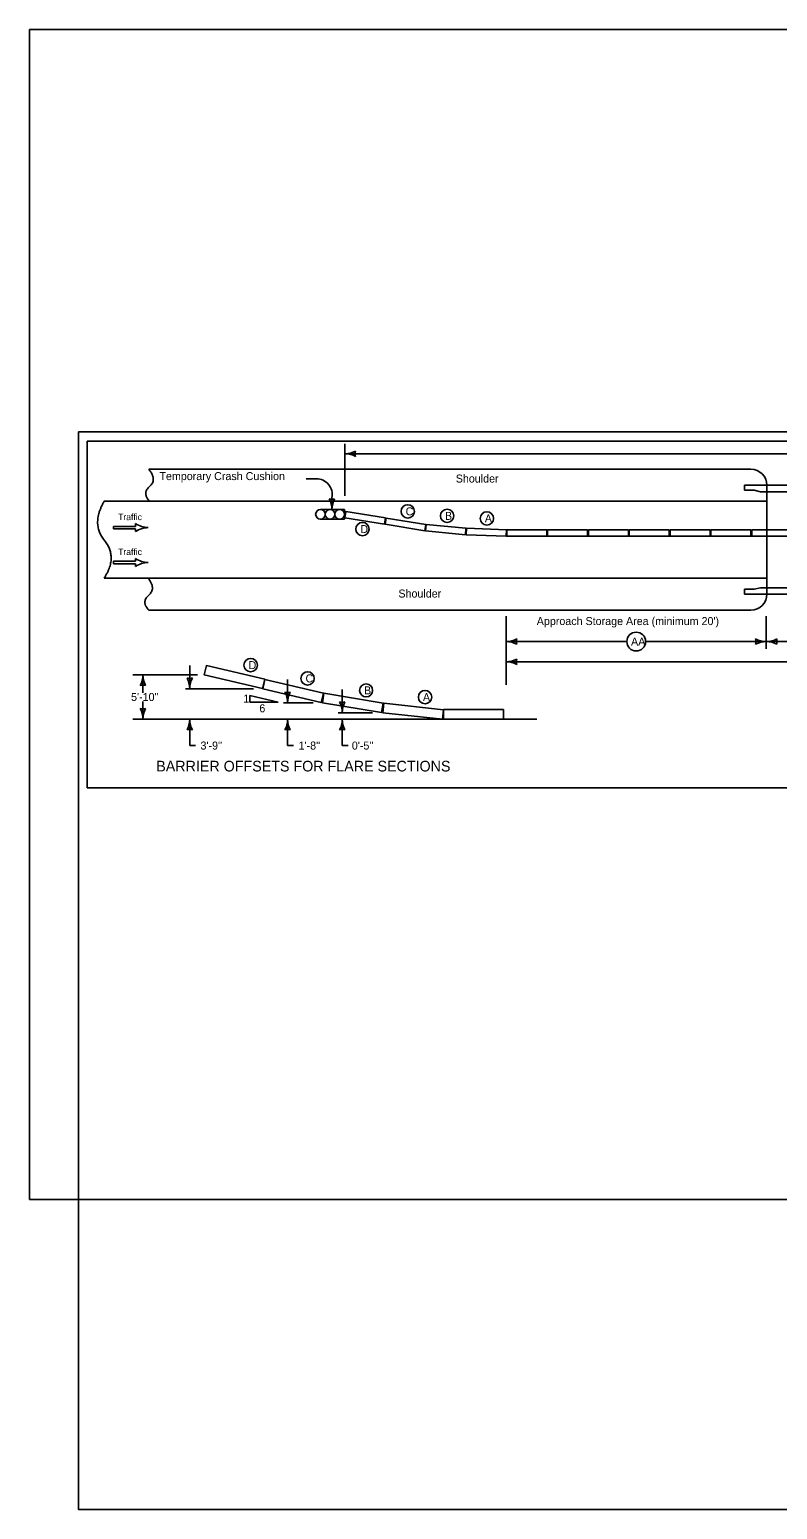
# Model space of a CAD drawing. Extents: x 10041 to 81668, y 7924 to 11018.
# Drawn here: x 10041 to 11442, y 7924 to 10698 of the extents above; entities that cross this region are included whole.
import ezdxf

# ---------------------------------------------------------------- set-up
doc = ezdxf.new("R2010")
doc.units = 0
for name, color, linetype in [('dsnCellElements', 7, 'Continuous'), ('Level 1', 7, 'Continuous'), ('Level 10', 7, 'Continuous'), ('Level 12', 7, 'Continuous'), ('Level 5', 7, 'Continuous'), ('Level 6', 7, 'Continuous'), ('SheetBorder', 7, 'Continuous'), ('ShtPlotIdentification', 7, 'Continuous')]:
    doc.layers.add(name, color=color, linetype=linetype)

msp = doc.modelspace()

# ---------------------------------------------------------------- linework, layer by layer
at = {"layer": 'dsnCellElements'}
msp.add_lwpolyline([(10041.2, 8505), (13362.1, 8505), (13362.1, 10698.4), (10041.2, 10698.4)], close=True, dxfattribs=at)
at = {"layer": 'Level 1'}
for p, q in [((10632, 9921.7), (10632, 9824.3)), ((10632, 9903.1), (11510.6, 9903.1)), ((10264.4, 9874.1), (11392.9, 9874.1)), ((10578.3, 9856.4), (10559.5, 9856.4)), ((11422.9, 9844.1), (11380.9, 9844.1)), ((11380.9, 9844.1), (11380.9, 9835.1)), ((11380.9, 9835.1), (11398.9, 9835.1)), ((11410.9, 9832.1), (11398.9, 9835.1)), ((11422.9, 9832.1), (11410.9, 9832.1)), ((11422.9, 9844.1), (11422.9, 9640.1)), ((11422.9, 9844.1), (11568.9, 9844.1)), ((11422.9, 9832.1), (11568.9, 9832.1)), ((10180.8, 9814.1), (11422.9, 9814.1)), ((10586.2, 9798.5), (10631.2, 9798.5)), ((10607.8, 9821), (10607.8, 9798.5)), ((10631.2, 9798.5), (10631.2, 9780.5)), ((10239.6, 9767), (10198.4, 9767)), ((10198.4, 9767), (10198.4, 9762.5)), ((10239.6, 9772.2), (10239.6, 9767)), ((10631.2, 9780.5), (10586.2, 9780.5)), ((10630, 9786.2), (10631.2, 9786)), ((10631.7, 9782.5), (10631.7, 9782.5)), ((10198.4, 9762.5), (10239.6, 9762.5)), ((10239.6, 9762.5), (10239.6, 9757.2)), ((10263.6, 9764.7), (10263.6, 9764.7)), ((10239.6, 9701.5), (10198.4, 9701.5)), ((10198.4, 9701.5), (10198.4, 9697)), ((10198.4, 9697), (10239.6, 9697)), ((10239.6, 9706.8), (10239.6, 9701.5)), ((10239.6, 9697), (10239.6, 9691.8)), ((10263.6, 9699.3), (10263.6, 9699.3)), ((10180.8, 9670.1), (11422.9, 9670.1)), ((11380.9, 9649.1), (11398.9, 9649.1)), ((11380.9, 9640.1), (11380.9, 9649.1)), ((11422.9, 9640.1), (11380.9, 9640.1)), ((11410.9, 9652.1), (11398.9, 9649.1)), ((11422.9, 9652.1), (11410.9, 9652.1)), ((11422.9, 9652.1), (11568.9, 9652.1)), ((11422.9, 9640.1), (11568.9, 9640.1)), ((10264.4, 9610.1), (11392.9, 9610.1)), ((10934.2, 9598.9), (10934.2, 9469.7)), ((11421.7, 9598.9), (11421.7, 9537.6)), ((10934.2, 9551.1), (11160.3, 9551.1)), ((11195.6, 9551.1), (11421.7, 9551.1)), ((11421.7, 9551.1), (11564.9, 9551.1)), ((10355.7, 9488.7), (10234.5, 9488.7)), ((10253.5, 9488.7), (10253.5, 9455.2)), ((10341.1, 9506.2), (10341.1, 9462.7)), ((10934.2, 9513.2), (11525, 9513.2)), ((10460.6, 9462.7), (10333.4, 9462.7)), ((10524.7, 9479.8), (10524.7, 9436.3)), ((10627.1, 9461.2), (10627.1, 9417.7)), ((10253.5, 9438.9), (10253.5, 9405.4)), ((10572.5, 9436.3), (10516.9, 9436.3)), ((10991.9, 9405.4), (10234.5, 9405.4)), ((10341.1, 9405.4), (10341.1, 9356.1)), ((10524.7, 9405.4), (10524.7, 9356.1)), ((10683.4, 9417.7), (10619.3, 9417.7)), ((10627.1, 9405.4), (10627.1, 9378.5)), ((10627.1, 9378.5), (10627.1, 9356.1)), ((10341.1, 9356.1), (10352.3, 9356.1)), ((10524.7, 9356.1), (10535.8, 9356.1)), ((10627.1, 9356.1), (10638.2, 9356.1))]:
    msp.add_line(p, q, dxfattribs=at)
for points in [[(10708, 9783), (10634, 9795.1), (10632, 9783.2), (10706, 9771.1)], [(10783.5, 9770.6), (10709.5, 9782.7), (10707.5, 9770.9), (10781.5, 9758.7)], [(10858.9, 9763.4), (10784.2, 9770.5), (10783.1, 9758.5), (10857.8, 9751.4)], [(10934.7, 9760.4), (10859.7, 9763.4), (10859.3, 9751.4), (10934.2, 9748.4)], [(10935.4, 9760.4), (11010.4, 9760.4), (11010.4, 9748.4), (10935.4, 9748.4)], [(11011.9, 9760.4), (11086.9, 9760.4), (11086.9, 9748.4), (11011.9, 9748.4)], [(11088.4, 9760.4), (11163.4, 9760.4), (11163.4, 9748.4), (11088.4, 9748.4)], [(11164.9, 9760.4), (11239.9, 9760.4), (11239.9, 9748.4), (11164.9, 9748.4)], [(11241.4, 9760.4), (11316.4, 9760.4), (11316.4, 9748.4), (11241.4, 9748.4)], [(11317.9, 9760.4), (11392.9, 9760.4), (11392.9, 9748.4), (11317.9, 9748.4)], [(11394.4, 9760.4), (11469.4, 9760.4), (11469.4, 9748.4), (11394.4, 9748.4)], [(10481.9, 9480.3), (10372.4, 9506.2), (10368.3, 9488.7), (10477.8, 9462.8)], [(10591.7, 9454.3), (10482.2, 9480.2), (10478.1, 9462.7), (10587.5, 9436.8)], [(10703.8, 9435.6), (10592.8, 9454.1), (10589.8, 9436.3), (10700.8, 9417.9)], [(10816.9, 9423.3), (10705, 9435.6), (10703.1, 9417.7), (10814.9, 9405.4)], [(10929.4, 9423.4), (10816.9, 9423.4), (10816.9, 9405.4), (10929.4, 9405.4)]]:
    msp.add_lwpolyline(points, close=True, dxfattribs=at)
for centre, radius in [((10586.2, 9789.5), 9), ((10586.2, 9789.5), 9), ((10604.2, 9789.5), 9), ((10604.2, 9789.5), 9), ((10622.2, 9789.5), 9), ((10622.2, 9789.5), 9), ((10749.7, 9795.2), 12.5), ((10823.5, 9786.8), 12.5), ((10898, 9781.9), 12.5), ((10664.8, 9762), 12.5), ((11177.9, 9551.1), 17.6), ((10455.4, 9506.9), 12.5), ((10562.1, 9482), 12.5), ((10671.8, 9459.6), 12.2), ((10782.1, 9446.9), 12.5)]:
    msp.add_circle(centre, radius, dxfattribs=at)
for centre, radius, start, end in [((10632, 9945.6), 42.5, 270, 298.0725), ((10667.7, 9903.1), 16.4, 162.2666, 197.7334), ((10632, 9860.6), 42.5, 61.9275, 90), ((10578.3, 9826.4), 30, 349.6463, 90), ((11392.9, 9844.1), 30, 0, 90), ((10607.8, 9834.2), 16.4, 252.2666, 287.7333), ((10565.3, 9798.5), 42.5, 360, 28.0725), ((10650.3, 9798.5), 42.5, 151.9275, 180), ((10265.5, 9813), 48.4, 237.618, 267.648), ((10265.5, 9716.4), 48.4, 92.352, 122.382), ((10265.5, 9747.6), 48.4, 237.618, 267.648), ((10265.5, 9651), 48.4, 92.352, 122.382), ((11392.9, 9640.1), 30, 270, 360), ((10934.2, 9593.6), 42.5, 270, 298.0725), ((10934.2, 9508.6), 42.5, 61.9275, 90), ((10969.8, 9551.1), 16.4, 162.2666, 197.7334), ((11386.1, 9551.1), 16.4, 342.2666, 17.7333), ((11421.7, 9593.6), 42.5, 241.9275, 270), ((11421.7, 9508.6), 42.5, 90, 118.0725), ((11421.7, 9593.6), 42.5, 270, 298.0725), ((11421.7, 9508.6), 42.5, 61.9275, 90), ((11457.3, 9551.1), 16.4, 162.2666, 197.7334), ((10934.2, 9555.7), 42.5, 270, 298.0725), ((10969.8, 9513.2), 16.4, 162.2666, 197.7334), ((10211, 9488.7), 42.5, 331.9275, 0), ((10296, 9488.7), 42.5, 180, 208.0725), ((10934.2, 9470.7), 42.5, 61.9275, 90), ((10253.5, 9453.1), 16.4, 72.2666, 107.7334), ((10341.1, 9498.4), 16.4, 252.2666, 287.7334), ((10298.6, 9462.7), 42.5, 0, 28.0725), ((10383.6, 9462.7), 42.5, 151.9275, 180), ((10524.7, 9471.9), 16.4, 252.2666, 287.7334), ((10482.2, 9436.3), 42.5, 0, 28.0725), ((10567.2, 9436.3), 42.5, 151.9275, 180), ((10627.1, 9453.4), 16.4, 252.2666, 287.7334), ((10584.6, 9417.7), 42.5, 0, 28.0725), ((10669.6, 9417.7), 42.5, 151.9275, 180), ((10253.5, 9441.1), 16.4, 252.2666, 287.7334), ((10211, 9405.4), 42.5, 0, 28.0725), ((10296, 9405.4), 42.5, 151.9275, 180), ((10298.6, 9405.4), 42.5, 331.9275, 0), ((10383.6, 9405.4), 42.5, 180, 208.0725), ((10482.2, 9405.4), 42.5, 331.9275, 0), ((10567.2, 9405.4), 42.5, 180, 208.0725), ((10584.6, 9405.4), 42.5, 331.9275, 0), ((10669.6, 9405.4), 42.5, 180, 208.0725), ((10341.1, 9369.8), 16.4, 72.2666, 107.7334), ((10524.7, 9369.8), 16.4, 72.2666, 107.7334), ((10627.1, 9369.8), 16.4, 72.2666, 107.7334)]:
    msp.add_arc(centre, radius, start, end, dxfattribs=at)
for points in [[(10264.4, 9874.1), (10280.5, 9854.8), (10251.6, 9829.2), (10266, 9814.2)], [(10180.8, 9814.1), (10156.2, 9771.5), (10206.9, 9709.3), (10180.8, 9670.1)], [(10262.8, 9670.1), (10278.9, 9650.8), (10249.9, 9625.2), (10264.4, 9610.1)]]:
    msp.add_open_spline(points, degree=2, dxfattribs=at)
at = {"layer": 'Level 10'}
for p, q in [((10149.1, 9926.7), (13254.1, 9926.7)), ((10149.1, 9276.7), (10149.1, 9926.7))]:
    msp.add_line(p, q, dxfattribs=at)
at = {"layer": 'Level 12'}
for p, q in [((10506.7, 9437.7), (10454.1, 9450.2)), ((10454.1, 9450.2), (10454.1, 9437.7)), ((10454.1, 9437.7), (10506.7, 9437.7))]:
    msp.add_line(p, q, dxfattribs=at)
at = {"layer": 'Level 5'}
msp.add_line((13254.1, 9276.7), (10149.1, 9276.7), dxfattribs=at)
at = {"layer": 'SheetBorder'}
msp.add_lwpolyline([(10132.5, 9944), (13267.5, 9944), (13267.5, 7924), (10132.5, 7924)], close=True, dxfattribs=at)
at = {"layer": 'ShtPlotIdentification'}
msp.add_line((10149.1, 9926.7), (10149.1, 9926.7), dxfattribs=at)

# ---------------------------------------------------------------- texts
at = {"layer": 'Level 12'}
for s, height, p in [('Temporary Crash Cushion', 15, (10284.4, 9853.8)), ('Shoulder', 15, (10839.7, 9849.2)), ('C', 15, (10745.8, 9787.7)), ('B', 15, (10819.5, 9779.3)), ('Traffic', 12, (10207.1, 9778.7)), ('D', 15, (10660.9, 9754.5)), ('A', 15, (10894.1, 9774.4)), ('Traffic', 12, (10207.1, 9713.3)), ('Shoulder', 15, (10732.2, 9633.6)), ("Approach Storage Area (minimum 20')", 15, (10991.5, 9582)), ('AA', 15, (11168.2, 9543.6)), ('D', 15, (10451.5, 9499.4)), ('C', 15, (10558.2, 9474.5)), ('B', 15, (10667.8, 9452.1)), ("5'-10''", 15, (10231.3, 9439.7)), ('1', 15, (10441.5, 9436.6)), ('6', 15, (10471.7, 9418.5)), ('A', 15, (10778.2, 9439.4)), ("3'-9''", 15, (10361.4, 9348.6)), ("1'-8''", 15, (10545.2, 9348.6)), ("0'-5''", 15, (10645, 9348.6))]:
    msp.add_text(s, height=height, dxfattribs=at).set_placement(p)
at = {"layer": 'Level 6'}
msp.add_text('BARRIER OFFSETS FOR FLARE SECTIONS', height=20, dxfattribs=at).set_placement((10278.5, 9307.5))

doc.saveas('drawing.dxf')
